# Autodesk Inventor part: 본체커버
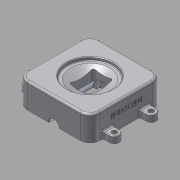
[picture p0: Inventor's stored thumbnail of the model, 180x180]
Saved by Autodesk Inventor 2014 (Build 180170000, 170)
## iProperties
Created: 2018-01
Part Number: 본체커버
Material: 알루미늄 6061
Document SubType Name: Modeling
Designer: mduedu
Density: 1 g/cm^3
Appearance: 알루미늄 - 평지
Author: mduedu
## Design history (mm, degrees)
sketch "스케치1"
  geometry: L1 (55, 55)-(-55, 55); L2 (-55, 55)-(-55, -55); L3 (-55, -55)-(55, -55); L4 (55, -55)-(55, 55); L5 (55, 55)-(-55, -55); L6 (-55, 55)-(55, -55); 1 further point
  constraints: 12 end point, 2 midpoint, 2 parallel, 1 horizontal, 1 perpendicular
  dimensions: "d0" = 110 distance of L3.end L2.end; "d1" = 110 distance of L2.end L1.end
extrude "돌출1" new body sketch "스케치1" distance "d2" = 38; taper "d3" = 0 deg
sketch "스케치2"
  geometry: L1 (-55, 55)-(55, 55) reference; L2 (-55, -55)-(-55, 55) reference; L3 (55, -55)-(-55, -55) reference; L4 (55, 55)-(55, -55) reference; L5 (0, 55)-(7.5, 55); L6 (7.5, 55)-(7.5, 36); L7 (7.5, 36)-(0, 36); L8 (0, 36)-(0, 55); L9 (0, 36)-(16, 36); L10 (16, 36)-(16, 22); L11 (16, 22)-(0, 22); L12 (0, 22)-(0, 36); L13 (0, 22)-(20, 22); L14 (20, 22)-(20, -25); L15 (20, -25)-(0, -25); L16 (0, -25)-(0, 22); L17 (0, -25)-(15, -25); L18 (15, -25)-(15, -30); L19 (15, -30)-(0, -30); L20 (0, -30)-(0, -25); 1 further point
  constraints: 32 end point, 8 parallel, 4 horizontal, 4 perpendicular, 1 midpoint
  dimensions: "d4" = 15 diameter of L6 L8; "d6" = 32 diameter of L10 L12; "d7" = 40 diameter of L14 L16; "d8" = 30 diameter of L18 L20; "d9" = 5 distance of L17.end L18.end; "d10" = 47 distance of L13.end L14.end; "d11" = 14 distance of L9.end L10.end; "d12" = 19 distance of L5.end L6.end
revolve "회전1" sketch "스케치2" stored, may be unused: angle "d13" = 90 deg
fillet "모깎기1" dims "d14" = 1
fillet "모깎기2" dims "d15" = 15
fillet "모깎기3" dims "d16" = 3
sketch "스케치3"
  geometry: L1 (-15, -17)-(15, -17); L2 (15, -17)-(15, 20); L3 (15, 20)-(-15, 20); L4 (-15, 20)-(-15, -17); L5 (-19, -22)-(19, -22) reference; L6 (19, 25)-(-19, 25) reference; 2 further points
  constraints: 8 end point, 2 parallel, 1 horizontal, 1 midpoint, 1 perpendicular, 1 vertical alignment
  dimensions: "d17" = 5 distance between parallel lines of L1 L5; "d18" = 5 distance between parallel lines of L6 L3; "d19" = 37 distance of L3.end L1.start (derived); "d20" = 30 distance between parallel lines of L2 L4
extrude "돌출2" cut sketch "스케치3" stored distance "d21" = 38; taper "d22" = 0 deg
fillet "모깎기4" dims "d23" = 3
sketch "스케치4"
  geometry: L1 (38, 35)-(33, 35); L2 (33, 35)-(33, 30); L3 (33, 30)-(26, 15); L4 (26, 15)-(26, 0); L5 (26, 0)-(38, 0); L6 (38, 0)-(38, 35); L7 (38, 40)-(38, -40) reference; 1 further point
  constraints: 12 end point, 2 parallel, 1 collinear, 1 horizontal, 1 horizontal alignment, 1 perpendicular
  dimensions: "d24" = 5 distance of L1.start L1.end; "d26" = 70 diameter of L1 L5; "d28" = 60 diameter of L2.end L5; "d29" = 30 diameter of L3.end L5; "d30" = 7 horizontal distance of L2.end L3.end
revolve "회전2" sketch "스케치4" stored, may be unused: angle "d31" = 90 deg
chamfer "모따기1" distance "d32" = 1; stored, may be unused: second distance "d33" = 2, angle "d34" = 45 deg
fillet "모깎기5" dims "d35" = 1
chamfer "모따기2" distance "d36" = 1; stored, may be unused: second distance "d37" = 2, angle "d38" = 45 deg
sketch "스케치5"
  geometry: L1 (7.5, 54)-(8.5, 55) reference; L2 (7.5, 54)-(7.5, 37) reference; L3 (8.5, 36)-(7.5, 37) reference; L4 (8.5, 36)-(15, 36) reference; L5 (16, 35)-(16, 22) reference; L6 (16, 22)-(19, 22) reference; L7 (20, 21)-(20, -24) reference; L8 (19, -25)-(15, -25) reference; L9 (15, -25)-(15, -29) reference; L10 (14, -30)-(-14, -30) reference; L11 (-15, -29)-(-15, -25) reference; L12 (-15, -25)-(-19, -25) reference; L13 (-20, -24)-(-20, 21) reference; L14 (-19, 22)-(-16, 22) reference; L15 (-16, 22)-(-16, 35) reference; L16 (-15, 36)-(-8.5, 36) reference; L17 (-7.5, 37)-(-8.5, 36) reference; L18 (-7.5, 37)-(-7.5, 54) reference; L19 (-8.5, 55)-(-7.5, 54) reference; L20 (-40, 55)-(-8.5, 55) reference; L21 (-55, -40)-(-55, 40) reference; L22 (40, -55)-(-40, -55) reference; L23 (55, 40)-(55, -40) reference; L24 (8.5, 55)-(40, 55) reference; L25 (55, 35.5)-(65, 35.5); L26 (65, 20.5)-(55, 20.5); L27 (55, 20.5)-(55, 35.5); L28 (55, 40)-(55, -40) reference; A1 r 1 centre (15, 35) between (16, 35) and (15, 36) reference; A2 r 1 centre (19, 21) between (20, 21) and (19, 22) reference; A3 r 1 centre (19, -24) between (19, -25) and (20, -24) reference; A4 r 1 centre (14, -29) between (14, -30) and (15, -29) reference; A5 r 1 centre (-14, -29) between (-15, -29) and (-14, -30) reference; A6 r 1 centre (-19, -24) between (-20, -24) and (-19, -25) reference; A7 r 1 centre (-19, 21) between (-19, 22) and (-20, 21) reference; A8 r 1 centre (-15, 35) between (-15, 36) and (-16, 35) reference; A9 r 15 centre (-40, 40) between (-40, 55) and (-55, 40) reference; A10 r 15 centre (-40, -40) between (-55, -40) and (-40, -55) reference; A11 r 15 centre (40, -40) between (40, -55) and (55, -40) reference; A12 r 15 centre (40, 40) between (55, 40) and (40, 55) reference; A13 r 7.5 centre (65, 28) between (65, 20.5) and (65, 35.5); 1 further point
  constraints: 6 end point, 2 point on circle, 2 tangent, 1 centre point, 1 collinear, 1 horizontal, 1 parallel, 1 point on line
  dimensions: "d39" = 15 distance between parallel lines of L26 L25; "d41" = 28 vertical distance of A13.centre point (0, 0); "d42" = 10 distance from line of A13.centre L23
extrude "돌출3" join sketch "스케치5" distance "d43" = 10; taper "d44" = 0 deg
fillet "모깎기6" dims "d45" = 1
fillet "모깎기7" dims "d46" = 3
sketch "스케치6"
  geometry: A1 r 7.5 centre (-65, 28) between (-65, 35.5) and (-65, 20.5) reference; A2 r 7.5 centre (-65, -28) between (-65, -20.5) and (-65, -35.5) reference; A3 r 7.5 centre (65, -28) between (65, -35.5) and (65, -20.5) reference; A4 r 7.5 centre (65, 28) between (65, 20.5) and (65, 35.5) reference; 5 further points
  constraints: 4 coincident
sketch "스케치7"
  geometry: 4 further points
  constraints: 4 other
hole "구멍1" sketch "스케치7" at (-65, 28), (65, 28), (-65, -28), (65, -28) diameter "d47" = 4.5; stored, may be unused: countersink angle "d51" = 90 deg, drill point angle "d53" = 0 deg; dims "d48" = 6, "d49" = 8, "d50" = 4.6, "d52" = 8
sketch "스케치8"
  geometry: L1 (-95, 35)-(-95, 0) reference; L2 (0, 38)-(-80, 38) reference; 2 further points
  constraints: 1 other
  dimensions: "d54" = 55 distance from line of point (-40, 23) L1; "d55" = 15 distance from line of point (-40, 23) L2
feature "엠보싱1" sketch "스케치8" dims "d0" = 110, "d1" = 110, "d56" = 0.5, "d57" = 0
node "솔리드1"
mirror "대칭1"
mirror "대칭2"
node "투영된 루프1"
node "투영된 루프2"
